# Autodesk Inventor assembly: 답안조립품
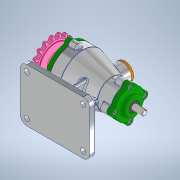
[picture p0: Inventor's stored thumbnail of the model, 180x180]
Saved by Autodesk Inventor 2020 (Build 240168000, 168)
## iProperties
Created: 2020-12
Part Number: 답안조립품
Document SubType Name: Assembly
Designer: USER
Author: USER
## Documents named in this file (15)
- C:\Users\USER\Desktop\701206V1035\답안조립품.iam
- C:\Users\USER\Desktop\701206V1035\본체.ipt
- C:\Users\USER\Desktop\701206V1035\개스킷 A.ipt
- C:\Users\USER\Desktop\701206V1035\개스킷 B.ipt
- C:\Users\USER\Desktop\701206V1035\뒤커버.ipt
- C:\Users\USER\Desktop\701206V1035\마개.ipt
- C:\Users\USER\Desktop\701206V1035\베어링 6200.ipt
- C:\Users\USER\Desktop\701206V1035\베어링 6203.ipt
- C:\Users\USER\Desktop\701206V1035\볼트 M5.ipt
- C:\Users\USER\Desktop\701206V1035\스프로킷.ipt
- C:\Users\USER\Desktop\701206V1035\앞커버.ipt
- C:\Users\USER\Desktop\701206V1035\오일 실 10 20 7.ipt
- C:\Users\USER\Desktop\701206V1035\오일 실 17 30 8.ipt
- C:\Users\USER\Desktop\701206V1035\축.ipt
- C:\Users\USER\Desktop\701206V1035\키 4x4x14.ipt
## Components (2 placed, 2 different names)
1. 개스킷 A:1
2. 개스킷 B:1
